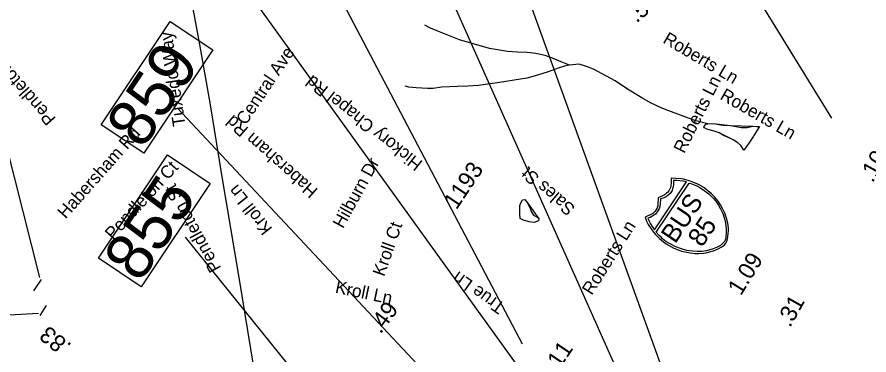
# Model space of a CAD drawing. Extents: x 1716282 to 1717158, y 799307 to 801078.
# Drawn here: x 1716608.3 to 1716700.7, y 799484.2 to 799520.8 of the extents above; entities that cross this region are included whole.
import ezdxf

# ---------------------------------------------------------------- set-up
doc = ezdxf.new("R2010")
doc.units = 0
for name, color, linetype in [('Exist Hydrographic Misc Water Feature', 7, 'Continuous'), ('Exist Road Non-System Type 51 Label', 7, 'Continuous'), ('Exist Road Primary Interstate Mileage Hundredths English Label', 7, 'Continuous'), ('Exist Road Primary Interstate Service Mileage Label', 7, 'Continuous'), ('Exist Road Primary Interstate Shield CELL', 7, 'Continuous'), ('Exist Road Primary Interstate Shield Number Label', 7, 'Continuous'), ('Exist Road Primary Interstate Structure Culvert Number Label', 7, 'Continuous'), ('Exist Road Primary Interstate Structure Ovrhead Sign CELL', 7, 'Continuous'), ('Exist Road Primary US Mileage Hundredths English Label', 7, 'Continuous'), ('Exist Road Primary US Structure Ovrhead Sign CELL', 7, 'Continuous'), ('Exist Road Primary US Structure Standard Bridge Number Label', 7, 'Continuous'), ('Exist Road Secondary Mileage Hundredths English Label', 7, 'Continuous'), ('Exist Road Secondary Mileage Tenths English Label', 7, 'Continuous'), ('Exist Road Secondary Structure Standard Bridge Number Label', 7, 'Continuous'), ('Exist Road Secondary Type 51 Number Label', 7, 'Continuous'), ('Exist Utilities Electrical Transmission Line', 7, 'Continuous')]:
    doc.layers.add(name, color=color, linetype=linetype)

msp = doc.modelspace()

# ---------------------------------------------------------------- linework, layer by layer
at = {"layer": 'Exist Hydrographic Misc Water Feature'}
for points in [[(1716668.211, 799515.587), (1716667.33, 799515.943), (1716666.361, 799516.325), (1716665.576, 799516.614), (1716664.556, 799516.819), (1716663.616, 799516.933), (1716662.563, 799516.987), (1716661.485, 799517.055), (1716659.526, 799517.375), (1716657.673, 799517.902), (1716656.302, 799518.313), (1716653.931, 799519.265), (1716653.138, 799519.595), (1716652.514, 799519.915)], [(1716668.211, 799515.587), (1716668.025, 799515.572), (1716667.097, 799515.294), (1716665.909, 799514.84), (1716664.747, 799514.475), (1716663.576, 799514.151), (1716660.634, 799513.702), (1716658.338, 799513.373), (1716657.187, 799513.282), (1716656.084, 799513.262), (1716654.368, 799513.169), (1716653.394, 799513.027), (1716652.806, 799513.041), (1716651.584, 799513.104), (1716650.772, 799513.201), (1716650.379, 799513.294)], [(1716683.209, 799509.207), (1716681.806, 799509.569), (1716679, 799510.606), (1716678.167, 799510.929), (1716677.015, 799511.505), (1716676.063, 799512.013), (1716674.505, 799512.974), (1716673.164, 799513.889), (1716670.821, 799515.139), (1716670.075, 799515.436), (1716669.258, 799515.679), (1716668.211, 799515.587)], [(1716688.174, 799507.886), (1716687.732, 799507.239), (1716687.339, 799506.665), (1716687.143, 799506.377), (1716686.802, 799506.856), (1716686.476, 799507.15), (1716685.974, 799507.494), (1716685.357, 799507.773), (1716684.924, 799507.963), (1716684.436, 799508.227), (1716683.923, 799508.402), (1716683.507, 799508.511), (1716683.105, 799508.644), (1716682.874, 799508.768), (1716682.786, 799508.896), (1716683.023, 799509.192), (1716683.209, 799509.207)], [(1716688.174, 799507.886), (1716687.732, 799507.239), (1716687.339, 799506.665), (1716687.143, 799506.377), (1716686.802, 799506.856), (1716686.476, 799507.15), (1716685.974, 799507.494), (1716684.436, 799508.227), (1716683.923, 799508.402), (1716683.507, 799508.511), (1716683.105, 799508.644), (1716682.874, 799508.768), (1716682.786, 799508.896), (1716683.023, 799509.192), (1716683.209, 799509.207)], [(1716683.209, 799509.207), (1716683.828, 799509.24), (1716684.864, 799509.058), (1716685.645, 799509.019), (1716686.095, 799508.958), (1716686.833, 799508.803), (1716687.5, 799508.804), (1716688.122, 799508.942), (1716688.5, 799508.929), (1716688.838, 799508.91), (1716688.206, 799507.934), (1716688.174, 799507.886)], [(1716683.209, 799509.207), (1716683.828, 799509.24), (1716685.645, 799509.019), (1716688.122, 799508.942), (1716688.5, 799508.929), (1716688.838, 799508.91), (1716688.206, 799507.934), (1716688.174, 799507.886)], [(1716662.865, 799498.969), (1716662.822, 799499.418), (1716662.833, 799500.361), (1716662.974, 799500.722), (1716663.114, 799500.978), (1716663.38, 799501.007), (1716663.658, 799500.642), (1716663.94, 799500.027), (1716664.065, 799499.696), (1716664.301, 799499.322), (1716664.719, 799499.109), (1716664.9, 799498.913), (1716664.858, 799498.698), (1716664.389, 799498.525), (1716663.835, 799498.588), (1716663.234, 799498.788), (1716662.865, 799498.969)], [(1716662.865, 799498.969), (1716662.822, 799499.418), (1716662.833, 799500.361), (1716662.974, 799500.722), (1716663.114, 799500.978), (1716663.38, 799501.007), (1716663.658, 799500.642), (1716664.9, 799498.913), (1716664.858, 799498.698), (1716664.389, 799498.525), (1716663.835, 799498.588), (1716663.234, 799498.788), (1716662.865, 799498.969)]]:
    msp.add_lwpolyline(points, dxfattribs=at)
at = {"layer": 'Exist Road Primary Interstate Shield CELL'}
for points in [[(1716685.182, 799496.291), (1716685.247, 799496.412), (1716685.32, 799496.586), (1716685.371, 799496.768), (1716685.41, 799496.988), (1716685.439, 799497.332), (1716685.456, 799497.613), (1716685.455, 799497.951), (1716685.38, 799498.457), (1716685.26, 799498.992), (1716685.071, 799499.519), (1716684.869, 799499.973), (1716684.599, 799500.434), (1716684.335, 799500.845), (1716683.995, 799501.259), (1716683.639, 799501.62), (1716683.238, 799501.951), (1716682.78, 799502.299), (1716682.222, 799502.626), (1716681.61, 799502.9), (1716681.21, 799503.041), (1716680.712, 799503.182), (1716680.379, 799503.248), (1716679.747, 799503.307), (1716679.239, 799503.32), (1716679.251, 799502.837), (1716679.221, 799502.547), (1716679.193, 799502.377), (1716679.129, 799502.225), (1716678.993, 799501.958), (1716678.883, 799501.807), (1716678.754, 799501.685), (1716678.646, 799501.581), (1716678.53, 799501.514), (1716677.829, 799501.212), (1716677.816, 799500.448), (1716677.793, 799500.302), (1716677.74, 799500.171), (1716677.697, 799500.04), (1716677.584, 799499.852), (1716677.486, 799499.715), (1716677.365, 799499.59), (1716677.265, 799499.492), (1716677.119, 799499.407), (1716676.411, 799499.094), (1716676.578, 799498.673), (1716676.767, 799498.293), (1716677.076, 799497.819), (1716677.335, 799497.479), (1716677.555, 799497.213), (1716677.994, 799496.774), (1716678.399, 799496.427), (1716678.705, 799496.209), (1716679.52, 799495.746), (1716679.991, 799495.554), (1716680.384, 799495.417), (1716681.3, 799495.221), (1716681.85, 799495.165), (1716682.265, 799495.156), (1716682.767, 799495.197), (1716683.017, 799495.234), (1716683.851, 799495.458), (1716684.338, 799495.653), (1716684.687, 799495.837), (1716684.829, 799495.938), (1716685.03, 799496.11)], [(1716676.704, 799498.991), (1716676.819, 799498.722), (1716676.992, 799498.385), (1716677.196, 799498.072), (1716677.428, 799497.736), (1716680.91, 799502.935), (1716680.559, 799502.995), (1716680.201, 799503.047), (1716679.862, 799503.077), (1716679.512, 799503.073), (1716679.5, 799502.658), (1716679.458, 799502.379), (1716679.403, 799502.168), (1716679.339, 799502.002), (1716679.206, 799501.766), (1716679.133, 799501.67), (1716678.853, 799501.405), (1716678.626, 799501.251), (1716678.357, 799501.14), (1716678.094, 799501.079), (1716678.068, 799500.5), (1716678.026, 799500.264), (1716677.939, 799500.018), (1716677.814, 799499.768), (1716677.538, 799499.44), (1716677.256, 799499.226), (1716676.971, 799499.07)], [(1716681.187, 799502.794), (1716681.371, 799502.752), (1716681.749, 799502.61), (1716682.026, 799502.482), (1716682.343, 799502.33), (1716682.829, 799501.984), (1716683.326, 799501.617), (1716683.599, 799501.366), (1716683.833, 799501.118), (1716684.082, 799500.827), (1716684.396, 799500.415), (1716684.613, 799499.992), (1716684.837, 799499.496), (1716684.999, 799499.012), (1716685.063, 799498.806), (1716685.145, 799498.443), (1716685.197, 799497.846), (1716685.219, 799497.42), (1716685.193, 799496.947), (1716685.154, 799496.723), (1716685.062, 799496.494), (1716684.939, 799496.337), (1716684.752, 799496.172), (1716684.599, 799496.04), (1716684.17, 799495.813), (1716683.786, 799495.654), (1716683.072, 799495.438), (1716682.596, 799495.382), (1716682.081, 799495.378), (1716681.574, 799495.405), (1716680.942, 799495.495), (1716680.353, 799495.655), (1716679.755, 799495.884), (1716679.067, 799496.229), (1716678.675, 799496.479), (1716678.319, 799496.751), (1716678.148, 799496.917), (1716677.937, 799497.126), (1716677.628, 799497.471)]]:
    msp.add_lwpolyline(points, close=True, dxfattribs=at)
at = {"layer": 'Exist Road Primary Interstate Structure Culvert Number Label'}
msp.add_line((1716696.692, 799509.841), (1716675.627, 799543.977), dxfattribs=at)
at = {"layer": 'Exist Road Primary Interstate Structure Ovrhead Sign CELL'}
msp.add_line((1716679.102, 799460.155), (1716629.082, 799529.428), dxfattribs=at)
at = {"layer": 'Exist Road Primary US Structure Ovrhead Sign CELL'}
for p, q in [((1716610.75, 799492.574), (1716599.832, 799535.666)), ((1716610.107, 799491.114), (1716610.923, 799492.333)), ((1716610.778, 799488.454), (1716611.492, 799489.521)), ((1716610.601, 799488.678), (1716569.402, 799486.024))]:
    msp.add_line(p, q, dxfattribs=at)
at = {"layer": 'Exist Road Primary US Structure Standard Bridge Number Label'}
for p, q in [((1716684.825, 799456.904), (1716642.845, 799550.908)), ((1716688.898, 799453.424), (1716660.168, 799532.74)), ((1716679.401, 799453.638), (1716625.661, 799510.959)), ((1716654.341, 799462.534), (1716626.546, 799496.937))]:
    msp.add_line(p, q, dxfattribs=at)
for points in [[(1716617.398, 799509.121), (1716624.891, 799520.315), (1716629.519, 799517.217), (1716622.027, 799506.023)], [(1716617.114, 799494.655), (1716624.607, 799505.849), (1716629.235, 799502.751), (1716621.743, 799491.557)]]:
    msp.add_lwpolyline(points, close=True, dxfattribs=at)
at = {"layer": 'Exist Road Secondary Structure Standard Bridge Number Label'}
msp.add_line((1716663.13, 799485.34), (1716638.264, 799532.543), dxfattribs=at)
at = {"layer": 'Exist Utilities Electrical Transmission Line'}
msp.add_lwpolyline([(1716633.977, 799482.851), (1716632.367, 799492.558), (1716630.53, 799503.475), (1716629.29, 799511.268), (1716628.107, 799517.821), (1716626.852, 799524.679), (1716625.789, 799531.257), (1716625.556, 799533.006), (1716621.858, 799539.178), (1716618.954, 799544.003), (1716616.581, 799547.965), (1716615.826, 799553.098), (1716614.633, 799561.317), (1716613.308, 799568.323), (1716612.046, 799574.971), (1716610.798, 799581.889), (1716609.353, 799590.917)], dxfattribs=at)

# ---------------------------------------------------------------- texts
at = {"layer": 'Exist Road Non-System Type 51 Label'}
for s, rotation, p in [('Tuxedo Way', 98.35908, (1716626.572, 799509.039)), ('Roberts Ln', 329.48692, (1716678.247, 799518.053)), ('Pendleton St', 131.39608, (1716612.577, 799509.8)), ('Central Ave', 56.20506, (1716633.092, 799508.984)), ('Hickory Chapel Rd', 141.79877, (1716652.381, 799505.089)), ('Roberts Ln', 63.37161, (1716680.662, 799505.917)), ('Roberts Ln', 330.19366, (1716684.447, 799511.943)), ('Habersham Rd', 138.61784, (1716641.013, 799502.077)), ('Habersham Rd', 48.43547, (1716613.56, 799498.839)), ('Pendleton Ct', 47.63931, (1716618.701, 799496.547)), ('Hilburn Dr', 61.18528, (1716643.647, 799497.784)), ('Sales St', 139.35177, (1716668.934, 799500.177)), ('Pendleton St', 118.53758, (1716630.463, 799493.577)), ('Kroll Ln', 128.36348, (1716636.043, 799497.853)), ('Kroll Ct', 70.63379, (1716648.104, 799492.593)), ('Roberts Ln', 57.71385, (1716670.645, 799490.561)), ('True Ln', 144.56816, (1716661.334, 799489.629)), ('Kroll Ln', 348.16785, (1716642.726, 799490.918))]:
    msp.add_text(s, height=1.3775, rotation=rotation, dxfattribs=at).set_placement(p)
at = {"layer": 'Exist Road Primary Interstate Mileage Hundredths English Label'}
msp.add_text('1.09', height=1.8125, rotation=58.36513, dxfattribs=at).set_placement((1716686.808, 799490.513))
at = {"layer": 'Exist Road Primary Interstate Service Mileage Label'}
for s, rotation, p in [('.10', 61.41471, (1716701.119, 799502.735)), ('.31', 60.643, (1716692.143, 799487.056))]:
    msp.add_text(s, height=1.8125, rotation=rotation, dxfattribs=at).set_placement(p)
at = {"layer": 'Exist Road Primary Interstate Shield Number Label'}
for s, p in [('BUS', (1716679.689, 799496.139)), ('85', (1716682.594, 799495.753))]:
    msp.add_text(s, height=2.03, rotation=56.20506, dxfattribs=at).set_placement(p)
at = {"layer": 'Exist Road Primary US Mileage Hundredths English Label'}
msp.add_text('.83', height=1.8125, rotation=140.64185, dxfattribs=at).set_placement((1716614.298, 799485.283))
at = {"layer": 'Exist Road Primary US Structure Standard Bridge Number Label'}
for s, p in [('859', (1716621.89, 799506.334)), ('855', (1716621.606, 799491.867))]:
    msp.add_text(s, height=5.075, rotation=56.20506, dxfattribs=at).set_placement(p)
at = {"layer": 'Exist Road Secondary Mileage Hundredths English Label'}
msp.add_text('.49', height=1.8125, rotation=53.52678, dxfattribs=at).set_placement((1716647.73, 799486.376))
at = {"layer": 'Exist Road Secondary Mileage Tenths English Label'}
msp.add_text('.55', height=1.8125, rotation=40.14223, dxfattribs=at).set_placement((1716675.493, 799520.079))
at = {"layer": 'Exist Road Secondary Type 51 Number Label'}
for s, p in [('1193', (1716655.951, 799499.822)), ('1311', (1716665.684, 799480.404))]:
    msp.add_text(s, height=1.8125, rotation=56.20506, dxfattribs=at).set_placement(p)

doc.saveas('drawing.dxf')
